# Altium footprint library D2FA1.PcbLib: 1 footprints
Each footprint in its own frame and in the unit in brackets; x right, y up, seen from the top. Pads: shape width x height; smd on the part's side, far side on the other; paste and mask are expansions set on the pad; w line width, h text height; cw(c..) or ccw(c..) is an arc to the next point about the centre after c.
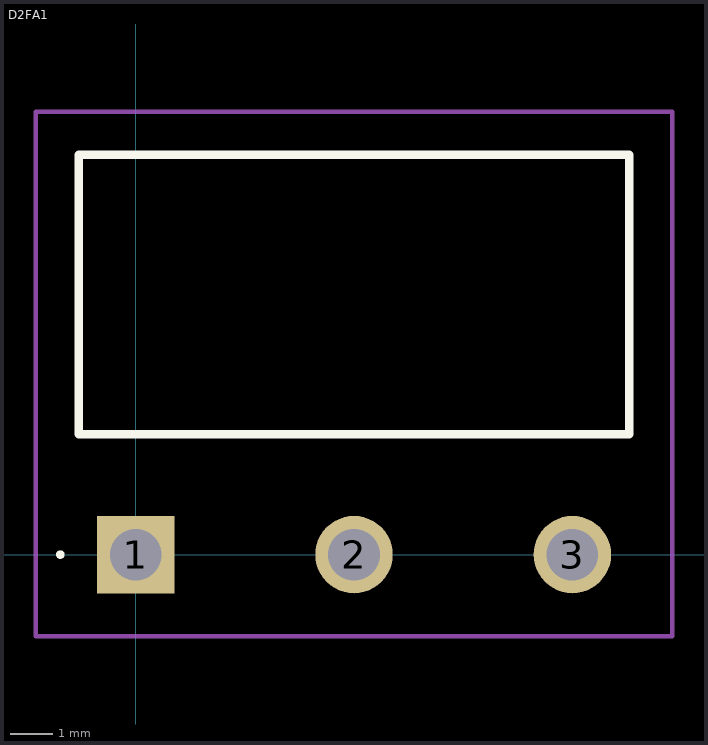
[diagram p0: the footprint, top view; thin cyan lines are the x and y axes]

## D2FA1 [mm]
pads (3):
  rect 1.8x1.8 hole 1.2: 1(0,0)
  round 1.8 hole 1.2: 2(5.08,0) 3(10.16,0)
Top Overlay:
  lines w0.1: -1.8,0 cw(c-1.75,0) -1.7,0 ; -1.8,0 -1.8,0 ; -1.8,0 ccw(c-1.75,0) -1.7,0 ; -1.7,0 -1.7,0
  lines w0.2: -1.32,2.8 11.48,2.8 11.48,9.3 -1.32,9.3 -1.32,2.8
Mechanical 15:
  lines w0.1: -1.32,2.8 11.48,2.8 11.48,9.3 -1.32,9.3 -1.32,2.8
Mechanical 20:
  lines w0.1: -2.32,-1.9 12.48,-1.9 12.48,10.3 -2.32,10.3 -2.32,-1.9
